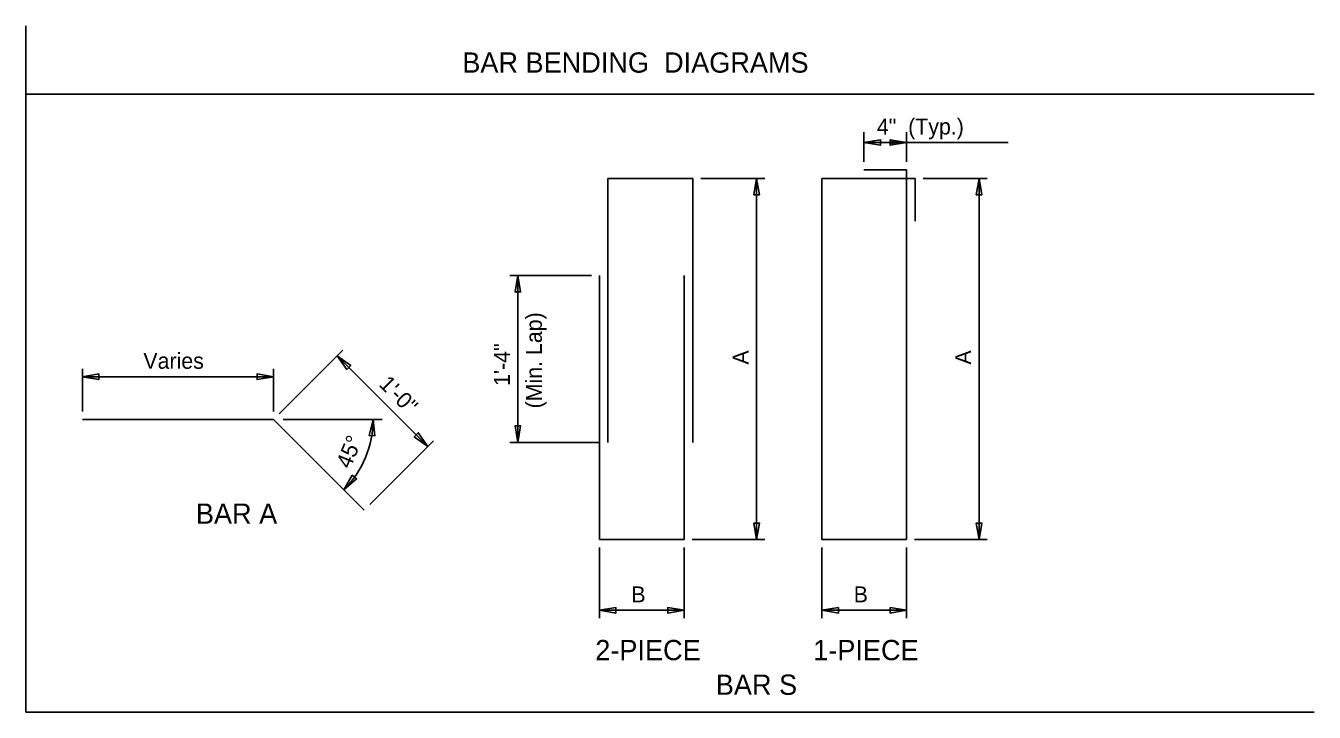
# Model space of a CAD drawing. Extents: x 0.3 to 30.8, y 0.1 to 19.8.
# Drawn here: x 18.58 to 30.79, y 13.3 to 19.8 of the extents above; entities that cross this region are included whole.
import ezdxf

# ---------------------------------------------------------------- set-up
doc = ezdxf.new("R2010")
doc.units = 0
for name, color, linetype in [('Dimension', 7, 'Continuous'), ('Rebar', 7, 'Continuous'), ('Rebar_h', 7, 'Continuous'), ('TextStructures', 7, 'Continuous')]:
    doc.layers.add(name, color=color, linetype=linetype)

msp = doc.modelspace()

# ---------------------------------------------------------------- linework, layer by layer
at = {"layer": 'Dimension'}
for p, q in [((18.58, 19.8), (18.58, 13.298)), ((18.58, 19.151), (30.788, 19.151)), ((26.521, 18.512), (26.521, 18.792)), ((26.521, 18.695), (27.887, 18.695)), ((26.926, 18.512), (26.926, 18.792)), ((24.976, 18.355), (25.581, 18.355)), ((25.505, 14.934), (25.505, 18.355)), ((27.083, 18.355), (27.688, 18.355)), ((27.613, 14.934), (27.613, 18.355)), ((23.94, 17.435), (23.167, 17.435)), ((23.243, 15.854), (23.243, 17.435)), ((20.981, 16.126), (21.584, 16.728)), ((21.53, 16.675), (22.389, 15.816)), ((19.116, 16.148), (19.116, 16.551)), ((20.928, 16.148), (20.928, 16.551)), ((19.116, 16.475), (20.928, 16.475)), ((21.02, 16.072), (21.957, 16.072)), ((21.84, 15.267), (22.443, 15.869)), ((24.021, 15.854), (23.167, 15.854)), ((24.895, 14.934), (25.581, 14.934)), ((27.002, 14.934), (27.688, 14.934)), ((24.016, 14.858), (24.016, 14.188)), ((24.819, 14.858), (24.819, 14.188)), ((26.123, 14.858), (26.123, 14.188)), ((26.926, 14.858), (26.926, 14.188)), ((24.016, 14.264), (24.819, 14.264)), ((26.123, 14.264), (26.926, 14.264)), ((18.58, 13.298), (30.788, 13.298))]:
    msp.add_line(p, q, dxfattribs=at)
for points in [[(26.521, 18.695), (26.678, 18.668), (26.678, 18.721)], [(26.926, 18.695), (26.77, 18.721), (26.77, 18.668)], [(26.837, 18.695), (26.785, 18.686), (26.785, 18.703)], [(25.505, 18.355), (25.479, 18.199), (25.532, 18.199)], [(27.613, 18.355), (27.586, 18.199), (27.639, 18.199)], [(23.243, 17.435), (23.216, 17.279), (23.269, 17.279)], [(21.53, 16.675), (21.622, 16.545), (21.659, 16.583)], [(19.116, 16.475), (19.272, 16.449), (19.272, 16.502)], [(20.928, 16.475), (20.772, 16.502), (20.772, 16.449)], [(21.871, 16.072), (21.834, 15.918), (21.887, 15.915)], [(23.243, 15.854), (23.269, 16.01), (23.216, 16.01)], [(22.389, 15.816), (22.298, 15.945), (22.26, 15.907)], [(21.595, 15.406), (21.715, 15.508), (21.674, 15.542)], [(25.505, 14.934), (25.532, 15.09), (25.479, 15.09)], [(27.613, 14.934), (27.639, 15.09), (27.586, 15.09)], [(24.016, 14.264), (24.172, 14.237), (24.172, 14.29)], [(24.819, 14.264), (24.663, 14.29), (24.663, 14.237)], [(26.123, 14.264), (26.279, 14.237), (26.279, 14.29)], [(26.926, 14.264), (26.77, 14.29), (26.77, 14.237)]]:
    msp.add_lwpolyline(points, close=True, dxfattribs=at)
msp.add_arc((20.928, 16.072), 0.943, 315.0017, 360, dxfattribs=at)
at = {"layer": 'Rebar'}
for p, q in [((26.521, 18.436), (26.926, 18.436)), ((26.926, 18.436), (26.926, 14.934)), ((26.123, 18.355), (27.007, 18.355)), ((26.123, 18.355), (26.123, 14.934)), ((27.007, 18.355), (27.007, 17.95)), ((19.116, 16.072), (20.928, 16.072)), ((20.928, 16.072), (21.787, 15.213)), ((26.123, 14.934), (26.926, 14.934))]:
    msp.add_line(p, q, dxfattribs=at)
at = {"layer": 'Rebar_h'}
for p, q in [((24.096, 18.355), (24.9, 18.355)), ((24.096, 18.355), (24.096, 15.854)), ((24.9, 18.355), (24.9, 15.854)), ((24.016, 17.435), (24.016, 14.934)), ((24.819, 17.435), (24.819, 14.934)), ((24.016, 14.934), (24.819, 14.934))]:
    msp.add_line(p, q, dxfattribs=at)

# ---------------------------------------------------------------- texts
at = {"layer": 'TextStructures'}
for s, height, p in [('BAR BENDING  DIAGRAMS', 0.192, (22.716, 19.356)), ('4"  (Typ.)', 0.1512, (26.644, 18.77)), ('Varies', 0.1512, (19.694, 16.551)), ('BAR A', 0.192, (20.192, 15.083)), ('B', 0.151, (24.318, 14.339)), ('B', 0.151, (26.425, 14.339)), ('2-PIECE', 0.192, (23.976, 13.791)), ('1-PIECE', 0.192, (26.041, 13.791)), ('BAR S', 0.192, (25.118, 13.463))]:
    msp.add_text(s, height=height, dxfattribs=at).set_placement(p)
for s, height, rotation, p in [('(Min. Lap)', 0.1512, 90, (23.47, 16.176)), ('1\'-4"', 0.1512, 90, (23.167, 16.389)), ('A', 0.151, 90, (25.43, 16.591)), ('A', 0.151, 90, (27.537, 16.591)), ('1\'-0"', 0.1512, 315, (21.917, 16.395)), ('45°', 0.1512, 67.5001, (21.654, 15.596))]:
    msp.add_text(s, height=height, rotation=rotation, dxfattribs=at).set_placement(p)

doc.saveas('drawing.dxf')
